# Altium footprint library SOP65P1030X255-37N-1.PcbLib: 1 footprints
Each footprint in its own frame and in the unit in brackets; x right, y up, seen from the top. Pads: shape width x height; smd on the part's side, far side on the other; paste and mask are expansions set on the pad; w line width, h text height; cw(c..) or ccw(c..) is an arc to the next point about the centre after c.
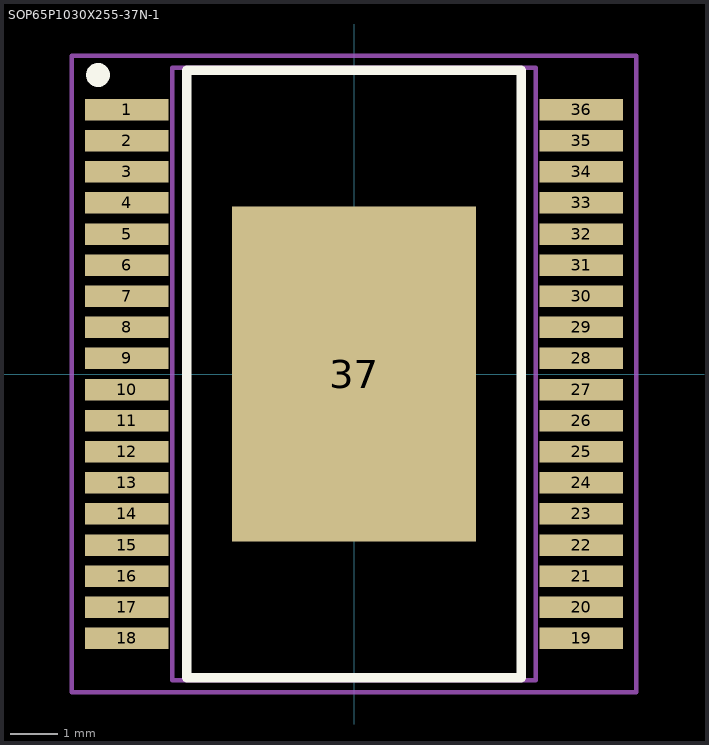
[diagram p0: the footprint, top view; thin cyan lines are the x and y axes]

## SOP65P1030X255-37N-1 [mm] "SOP,0.65mm pitch;36 pin,7.50mm W X 12.70mm L X 2.55mm H body (w/thermal tab)"
height 2.55
pads (37):
  rect 1.75x0.45 smd paste+0 mask+0: 1(-4.75,5.525) 2(-4.75,4.875) 3(-4.75,4.225) 4(-4.75,3.575) 5(-4.75,2.925) 6(-4.75,2.275) 7(-4.75,1.625) 8(-4.75,0.975) 9(-4.75,0.325) 10(-4.75,-0.325) 11(-4.75,-0.975) 12(-4.75,-1.625) 13(-4.75,-2.275) 14(-4.75,-2.925) 15(-4.75,-3.575) 16(-4.75,-4.225) 17(-4.75,-4.875) 18(-4.75,-5.525) 19(4.75,-5.525) 20(4.75,-4.875) 21(4.75,-4.225) 22(4.75,-3.575) 23(4.75,-2.925) 24(4.75,-2.275) 25(4.75,-1.625) 26(4.75,-0.975) 27(4.75,-0.325) 28(4.75,0.325) 29(4.75,0.975) 30(4.75,1.625) 31(4.75,2.275) 32(4.75,2.925) 33(4.75,3.575) 34(4.75,4.225) 35(4.75,4.875) 36(4.75,5.525)
  rect 5.1x7 smd paste+0 mask+0: 37(0,0)
Top Overlay:
  circle w0.25: c-5.35,6.25 r0.125
  lines w0.2: -3.5,-6.35 -3.5,6.35 3.5,6.35 3.5,-6.35 -3.5,-6.35
M3 (ASY_Text_Top):
  text ".DESIGNATOR" at 0,0 h1.2
M13 (CMP_Body_OTL_Top):
  lines w0.1: -3.8,-6.4 -3.8,6.4 3.8,6.4 3.8,-6.4 -3.8,-6.4
M15 (CMP_Courtyard_Top):
  lines w0.1: -0.5,0 0.5,0 ; 0,-0.5 0,0.5 ; -5.9,-6.65 -5.9,6.65 5.9,6.65 5.9,-6.65 -5.9,-6.65
3D body "PG-DSO-36-51.stp": height 2.56, standoff 0, extent -5.15,-6.4 5.15,6.4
